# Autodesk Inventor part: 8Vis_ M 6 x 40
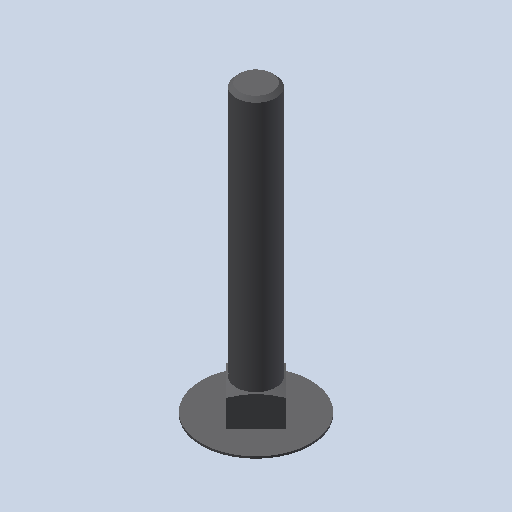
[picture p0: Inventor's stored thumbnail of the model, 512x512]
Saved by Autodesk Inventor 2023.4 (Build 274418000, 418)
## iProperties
Created: 2011-01
Part Number: 8Vis_ M 6 x 40
Document SubType Name: Modeling
Designer: eric
Density: 1 g/cm^3
Mass: 1.54113 g
Surface Area: 12.9148 cm^2
Volume: 1.54113 cm^3
Material: Générique
Appearance: Red
Author: eric
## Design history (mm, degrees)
feature "Base1"
node "Corps solides"
node "Corps surfaciques"
node "Solide1"
